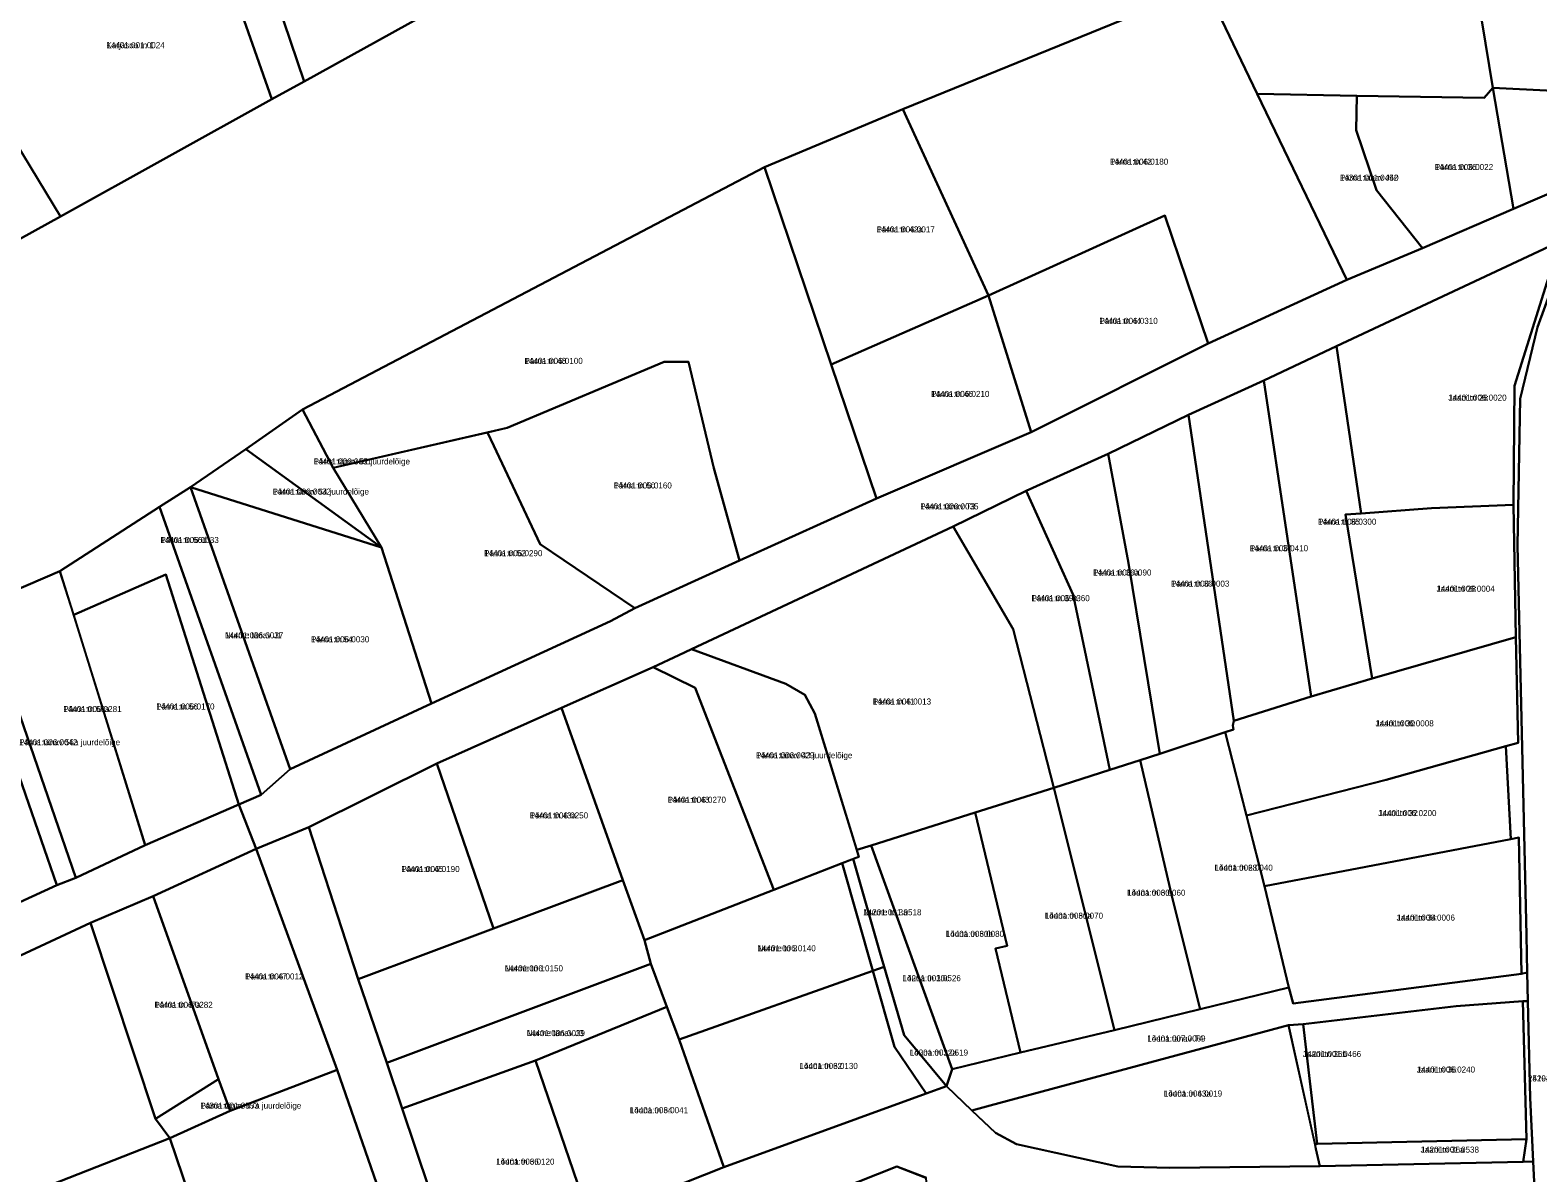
# Model space of a CAD drawing. Extents: x 640657 to 665127, y 6395726 to 6426831.
# Drawn here: x 649552.6 to 649927.6, y 6411820.4 to 6412104.6 of the extents above; entities that cross this region are included whole.
import ezdxf

# ---------------------------------------------------------------- set-up
doc = ezdxf.new("R2010")
doc.units = 0
for name, color, linetype in [('L_AADRESS', 7, 'Continuous'), ('PIIR', 7, 'Continuous'), ('TUNNUS', 7, 'Continuous')]:
    doc.layers.add(name, color=color, linetype=linetype)

msp = doc.modelspace()

# ---------------------------------------------------------------- linework, layer by layer
at = {"layer": 'PIIR'}
for points in [[(649378.03, 6411957.6), (649560.17, 6412058.25), (649612.7, 6412087.46), (649620.75, 6412091.85), (649650.44, 6412108.25), (649668.58, 6412116.67), (649691.67, 6412127.38), (649718.88, 6412138.69), (649748.94, 6412151.16), (649770.59, 6412160.14), (649810.5, 6412176.7), (649842.91, 6412190.15), (649874.08, 6412203.09), (649950.67, 6412234.89)], [(649966.63, 6412168.97), (649907.99, 6412141.34), (649844.88, 6412115.63), (649769.67, 6412084.97), (649735.24, 6412070.53), (649620.31, 6412010.25), (649606.21, 6412000.36), (649592.49, 6411990.94), (649584.81, 6411986.06), (649559.96, 6411970.08), (649540.51, 6411961.7)], [(649933.03, 6412052.06), (649877.52, 6412026), (649859.42, 6412017.5), (649840.64, 6412008.94), (649820.71, 6411999.22), (649800.34, 6411990), (649782.11, 6411981.17), (649717.09, 6411950.68), (649713.95, 6411949.19), (649707.53, 6411946.14), (649684.71, 6411936.04), (649653.72, 6411922.25), (649621.95, 6411906.37), (649608.8, 6411901), (649604.48, 6411912.01), (649610.06, 6411914.41), (649617.3, 6411920.82), (649652.39, 6411937.15), (649696.95, 6411957.65), (649703.01, 6411960.84), (649729.05, 6411972.66), (649763.1, 6411988.14), (649801.51, 6412004.58), (649845.57, 6412026.66), (649880.01, 6412042.47), (649898.84, 6412050.36), (649921.48, 6412060.15), (649934.02, 6412065.58)], [(649926.77, 6411814.86), (649926.38, 6411823.2), (649925.63, 6411839.07), (649925.1, 6411863.1), (649924.9, 6411870.2), (649924.73, 6411879.55), (649922.49, 6411976.44), (649923.17, 6412012.91), (649927.45, 6412030.71), (649935.7, 6412053.2)], [(649648.59, 6411789.41), (649628.94, 6411846.06), (649608.8, 6411901), (649621.95, 6411906.37), (649634.14, 6411868.56), (649641.33, 6411847.78), (649645.1, 6411836.4), (649658.55, 6411796.48)], [(649691.9, 6411808.65), (649725.14, 6411821.84), (649775.45, 6411840.16), (649780.5, 6411842), (649786.76, 6411835.93), (649792.65, 6411830.35), (649797.92, 6411827.51), (649823.13, 6411821.98), (649836.01, 6411821.63), (649873.34, 6411822.07), (649923.92, 6411823.15), (649926.38, 6411823.2), (649926.77, 6411814.86)], [(649775.5, 6411819.2), (649768.14, 6411821.97), (649730.09, 6411806.9)]]:
    msp.add_lwpolyline(points, dxfattribs=at)
for points in [[(649593.55, 6412141.97), (649586.4, 6412168.82), (649596.55, 6412170.1), (649613.03, 6412114.94), (649613.92, 6412111.92), (649620.75, 6412091.85), (649612.7, 6412087.46)], [(649907.99, 6412141.34), (649966.63, 6412168.97), (649944.74, 6412088.85), (649916.39, 6412090.28)], [(649524.06, 6412120.99), (649593.55, 6412141.97), (649612.7, 6412087.46), (649560.17, 6412058.25), (649535.55, 6412098.81)], [(649844.88, 6412115.63), (649907.99, 6412141.34), (649916.39, 6412090.28), (649914.19, 6412087.74), (649882.56, 6412088.24), (649857.79, 6412088.79)], [(649650.44, 6412108.25), (649620.75, 6412091.85), (649613.92, 6412111.92), (649618.8, 6412113.87), (649644.9, 6412124.06)], [(649769.67, 6412084.97), (649844.88, 6412115.63), (649857.79, 6412088.79), (649880.01, 6412042.47), (649845.57, 6412026.66), (649834.75, 6412058.52), (649790.94, 6412038.61)], [(649378.03, 6411957.6), (649387.65, 6412060.41), (649477.25, 6412088.89), (649479.92, 6412080.49), (649486.11, 6412082.25), (649535.55, 6412098.81), (649560.17, 6412058.25)], [(649857.79, 6412088.79), (649882.56, 6412088.24), (649882.38, 6412079.69), (649887.45, 6412064.8), (649898.84, 6412050.36), (649880.01, 6412042.47)], [(649882.56, 6412088.24), (649914.19, 6412087.74), (649916.39, 6412090.28), (649921.48, 6412060.15), (649898.84, 6412050.36), (649887.45, 6412064.8), (649882.38, 6412079.69)], [(649921.48, 6412060.15), (649916.39, 6412090.28), (649944.74, 6412088.85), (649939.25, 6412068.88), (649934.02, 6412065.58)], [(649735.24, 6412070.53), (649769.67, 6412084.97), (649790.94, 6412038.61), (649751.82, 6412021.41)], [(649620.31, 6412010.25), (649735.24, 6412070.53), (649751.82, 6412021.41), (649763.1, 6411988.14), (649729.05, 6411972.66), (649722.61, 6411995.65), (649716.35, 6412022.12), (649710.24, 6412022.07), (649671.22, 6412005.67), (649628, 6411995.77)], [(649790.94, 6412038.61), (649834.75, 6412058.52), (649845.57, 6412026.66), (649801.51, 6412004.58)], [(649883.62, 6411984.4), (649877.52, 6412026), (649933.03, 6412052.06), (649921.73, 6412016.17), (649921.49, 6411986.55), (649901.11, 6411985.71)], [(649935.7, 6412053.2), (649927.45, 6412030.71), (649923.17, 6412012.91), (649922.49, 6411976.44), (649924.73, 6411879.55), (649924.9, 6411870.2), (649923.51, 6411869.9), (649922.81, 6411903.79), (649920.86, 6411903.43), (649919.62, 6411926.52), (649922.7, 6411927.31), (649922.04, 6411953.62), (649921.49, 6411986.55), (649921.73, 6412016.17), (649933.03, 6412052.06)], [(649751.82, 6412021.41), (649790.94, 6412038.61), (649801.51, 6412004.58), (649763.1, 6411988.15)], [(649859.42, 6412017.5), (649877.52, 6412026), (649883.62, 6411984.4), (649879.68, 6411984.1), (649886.37, 6411943.31), (649871.2, 6411938.88)], [(649667.89, 6412001.23), (649666.33, 6412004.54), (649671.22, 6412005.67), (649710.24, 6412022.07), (649716.35, 6412022.12), (649722.61, 6411995.65), (649729.05, 6411972.66), (649703.01, 6411960.84), (649679.45, 6411976.75)], [(649851.97, 6411932.85), (649840.64, 6412008.94), (649859.42, 6412017.5), (649871.2, 6411938.88)], [(649606.21, 6412000.36), (649620.31, 6412010.25), (649628, 6411995.77), (649639.96, 6411975.96)], [(649840.64, 6412008.94), (649851.97, 6411932.85), (649851.71, 6411931.63), (649851.83, 6411930.66), (649849.82, 6411929.99), (649833.57, 6411924.64), (649825.73, 6411972.01), (649820.71, 6411999.22)], [(649639.96, 6411975.96), (649628, 6411995.77), (649666.33, 6412004.54), (649667.89, 6412001.23), (649679.45, 6411976.75), (649703.01, 6411960.84), (649696.95, 6411957.65), (649652.39, 6411937.15)], [(649592.49, 6411990.94), (649606.21, 6412000.36), (649639.96, 6411975.96)], [(649800.34, 6411990), (649820.71, 6411999.22), (649825.73, 6411972.01), (649833.57, 6411924.64), (649828.65, 6411923.03), (649821.1, 6411920.61), (649811.98, 6411964.14)], [(649584.81, 6411986.06), (649592.49, 6411990.94), (649617.3, 6411920.82), (649610.06, 6411914.41)], [(649592.49, 6411990.94), (649639.96, 6411975.96), (649652.39, 6411937.15), (649617.3, 6411920.82)], [(649782.11, 6411981.17), (649800.34, 6411990), (649811.98, 6411964.14), (649821.1, 6411920.61), (649807.22, 6411916.19), (649797.04, 6411955.66)], [(649559.96, 6411970.08), (649584.81, 6411986.06), (649610.06, 6411914.41), (649604.48, 6411912.01), (649586.36, 6411969.22), (649563.44, 6411959.16)], [(649921.49, 6411986.55), (649922.04, 6411953.62), (649886.37, 6411943.31), (649879.68, 6411984.1), (649883.62, 6411984.4), (649901.11, 6411985.71)], [(649782.11, 6411981.17), (649797.04, 6411955.66), (649807.22, 6411916.19), (649787.64, 6411910.04), (649761.73, 6411901.81), (649758.2, 6411900.7), (649747.73, 6411934.68), (649745.27, 6411939.26), (649740.53, 6411941.99), (649717.09, 6411950.68)], [(649559.96, 6411970.08), (649581.19, 6411901.91), (649563.96, 6411893.77), (649540.51, 6411961.7)], [(649563.44, 6411959.16), (649586.36, 6411969.22), (649604.48, 6411912.01), (649581.19, 6411901.91)], [(649535.8, 6411959.57), (649540.51, 6411961.7), (649563.96, 6411893.77), (649559.24, 6411891.92)], [(649515.01, 6411950.07), (649535.8, 6411959.57), (649559.24, 6411891.92), (649537.7, 6411882.08), (649535.3, 6411888.7), (649518.3, 6411941)], [(649707.53, 6411946.14), (649713.95, 6411949.19), (649717.09, 6411950.68), (649740.53, 6411941.99), (649745.27, 6411939.26), (649747.73, 6411934.68), (649758.68, 6411899.03), (649754.57, 6411897.43), (649737.58, 6411890.77), (649718, 6411941.02)], [(649922.04, 6411953.62), (649922.7, 6411927.31), (649919.62, 6411926.52), (649889.84, 6411918.12), (649855.11, 6411909.28), (649849.82, 6411929.99), (649851.83, 6411930.66), (649851.71, 6411931.63), (649851.97, 6411932.85), (649871.2, 6411938.88), (649886.37, 6411943.31)], [(649718, 6411941.02), (649737.58, 6411890.77), (649705.37, 6411878.3), (649700.02, 6411893.23), (649684.71, 6411936.04), (649707.53, 6411946.14)], [(649653.72, 6411922.25), (649684.71, 6411936.04), (649700.02, 6411893.23), (649667.86, 6411881.18)], [(649859.59, 6411891.74), (649865.64, 6411866.46), (649843.6, 6411861.14), (649836.67, 6411888.54), (649828.65, 6411923.03), (649833.57, 6411924.64), (649849.82, 6411929.99)], [(649855.11, 6411909.28), (649889.84, 6411918.12), (649919.62, 6411926.52), (649920.86, 6411903.43), (649859.59, 6411891.74)], [(649621.95, 6411906.37), (649653.72, 6411922.25), (649667.86, 6411881.18), (649634.14, 6411868.56)], [(649836.67, 6411888.54), (649843.6, 6411861.14), (649822.23, 6411855.89), (649807.22, 6411916.19), (649821.1, 6411920.61), (649828.65, 6411923.03)], [(649792.65, 6411876.17), (649795.61, 6411876.89), (649787.64, 6411910.04), (649807.22, 6411916.19), (649822.23, 6411855.89), (649798.89, 6411850.3)], [(649359.6, 6411800), (649461.18, 6411845.56), (649461.5, 6411845.7), (649492.04, 6411860.8), (649511.66, 6411869.3), (649537.7, 6411882.08), (649559.24, 6411891.92), (649563.96, 6411893.77), (649581.19, 6411901.91), (649604.48, 6411912.01), (649608.8, 6411901), (649583.2, 6411889.18), (649567.57, 6411882.62), (649537.67, 6411868.66), (649501.41, 6411851.98), (649491.81, 6411847.78), (649460.08, 6411833.74), (649365.41, 6411791.58), (649361.7, 6411789.91)], [(649787.64, 6411910.04), (649795.61, 6411876.89), (649792.65, 6411876.17), (649798.89, 6411850.3), (649781.86, 6411846.2), (649761.73, 6411901.81)], [(649758.68, 6411899.03), (649758.2, 6411900.7), (649761.73, 6411901.81), (649781.86, 6411846.2), (649780.5, 6411842), (649769.94, 6411854.67), (649764.96, 6411871.63), (649763.9, 6411875.25), (649757.26, 6411898.48)], [(649922.81, 6411903.79), (649923.51, 6411869.9), (649866.67, 6411862.49), (649865.64, 6411866.46), (649859.59, 6411891.74), (649920.86, 6411903.43)], [(649608.8, 6411901), (649628.94, 6411846.06), (649602.34, 6411835.82), (649599.45, 6411843.73), (649583.2, 6411889.18)], [(649757.26, 6411898.48), (649763.9, 6411875.25), (649764.96, 6411871.63), (649762.2, 6411870.66), (649754.57, 6411897.43)], [(649706.98, 6411872.42), (649705.37, 6411878.3), (649737.58, 6411890.77), (649754.57, 6411897.43), (649762.2, 6411870.66), (649714.03, 6411853.59), (649710.9, 6411861.7)], [(649634.14, 6411868.56), (649667.86, 6411881.18), (649700.02, 6411893.23), (649705.37, 6411878.3), (649706.98, 6411872.42), (649641.33, 6411847.78)], [(649567.57, 6411882.62), (649583.2, 6411889.18), (649599.45, 6411843.73), (649583.75, 6411833.86)], [(649492.1, 6411846.32), (649491.81, 6411847.78), (649501.41, 6411851.98), (649537.67, 6411868.66), (649567.57, 6411882.62), (649583.75, 6411833.86), (649587.32, 6411829.02), (649552.9, 6411815.48), (649514.43, 6411799.9), (649504.11, 6411795.75), (649503.76, 6411797.21), (649502.88, 6411801.17)], [(649641.33, 6411847.78), (649706.98, 6411872.42), (649710.9, 6411861.7), (649678.32, 6411848.32), (649645.1, 6411836.4)], [(649762.2, 6411870.66), (649764.96, 6411871.63), (649769.94, 6411854.67), (649780.5, 6411842), (649775.45, 6411840.16), (649767.53, 6411851.74)], [(649767.53, 6411851.74), (649775.45, 6411840.16), (649725.14, 6411821.84), (649714.03, 6411853.59), (649762.2, 6411870.66)], [(649781.86, 6411846.2), (649798.89, 6411850.3), (649822.23, 6411855.89), (649843.6, 6411861.14), (649865.64, 6411866.46), (649866.67, 6411862.49), (649923.51, 6411869.9), (649924.9, 6411870.2), (649925.1, 6411863.1), (649923.8, 6411863.1), (649907.2, 6411861.9), (649869.22, 6411857.39), (649865.54, 6411857.14), (649791.37, 6411837.17), (649786.76, 6411835.93), (649780.5, 6411842)], [(649678.32, 6411848.32), (649710.9, 6411861.7), (649714.03, 6411853.59), (649725.14, 6411821.84), (649691.9, 6411808.65)], [(649924.69, 6411828.8), (649872.69, 6411827.59), (649869.22, 6411857.39), (649907.2, 6411861.9), (649923.8, 6411863.1)], [(649925.1, 6411863.1), (649925.63, 6411839.07), (649926.38, 6411823.2), (649923.92, 6411823.15), (649924.69, 6411828.8), (649923.8, 6411863.1)], [(649786.76, 6411835.93), (649791.37, 6411837.17), (649865.54, 6411857.14), (649872.38, 6411826.38), (649873.34, 6411822.07), (649836.01, 6411821.63), (649823.13, 6411821.98), (649797.92, 6411827.51), (649792.65, 6411830.35)], [(649872.14, 6411827.47), (649865.54, 6411857.14), (649869.22, 6411857.39), (649872.69, 6411827.59)], [(649587.32, 6411829.02), (649602.34, 6411835.82), (649628.94, 6411846.06), (649648.59, 6411789.41), (649606.41, 6411772.84)], [(649658.55, 6411796.48), (649645.1, 6411836.4), (649678.32, 6411848.32), (649691.9, 6411808.65)], [(649602.34, 6411835.82), (649587.32, 6411829.02), (649583.75, 6411833.86), (649599.45, 6411843.73)], [(649552.9, 6411815.48), (649587.32, 6411829.02), (649606.41, 6411772.84), (649568.62, 6411758.44)], [(649872.14, 6411827.47), (649872.69, 6411827.59), (649924.69, 6411828.8), (649923.92, 6411823.15), (649873.34, 6411822.07), (649872.38, 6411826.38)], [(649730.09, 6411806.9), (649768.14, 6411821.97), (649775.35, 6411819.18), (649780.47, 6411751.28), (649746.12, 6411740.15), (649738.04, 6411783.15)]]:
    msp.add_lwpolyline(points, close=True, dxfattribs=at)

# ---------------------------------------------------------------- texts
at = {"layer": 'L_AADRESS'}
for s, p in [('Karjasoo tn 1', (649571.57, 6412100.11)), ('Pärna tn 42', (649821.13, 6412071.15)), ('Pärna tn 36', (649901.93, 6412069.81)), ('Pärna tänav J40', (649878.32, 6412067.17)), ('Pärna tn 42a', (649763.09, 6412054.29)), ('Pärna tn 44', (649818.52, 6412031.55)), ('Pärna tn 48', (649675.53, 6412021.6)), ('Pärna tn 46', (649776.66, 6412013.38)), ('Jaani tn 26', (649905.28, 6412012.46)), ('Pärna tänav 52 juurdelõige', (649623.09, 6411996.59)), ('Pärna tn 50', (649697.69, 6411990.61)), ('Pärna tänav 54 juurdelõige', (649612.89, 6411989.09)), ('Pärna tänav T3', (649773.96, 6411985.4)), ('Pärna tn 35', (649872.89, 6411981.6)), ('Pärna tn 56d', (649585.01, 6411977.06)), ('Pärna tn 37', (649855.92, 6411975)), ('Pärna tn 52', (649665.5, 6411973.77)), ('Pärna tn 39a', (649816.96, 6411968.96)), ('Pärna tn 39', (649836.34, 6411966.2)), ('Jaani tn 28', (649902.34, 6411964.93)), ('Pärna tn 39b', (649801.61, 6411962.58)), ('Nurme tänav J1', (649601.05, 6411953.35)), ('Pärna tn 54', (649622.44, 6411952.35)), ('Pärna tn 56a', (649560.85, 6411935)), ('Pärna tn 56', (649583.96, 6411935.64)), ('Pärna tn 41', (649762.16, 6411936.88)), ('Jaani tn 30', (649887.16, 6411931.45)), ('Pärna tänav 56a juurdelõige', (649549.88, 6411926.75)), ('Pärna tänav 43 juurdelõige', (649733.11, 6411923.5)), ('Pärna tn 43', (649711.14, 6411912.45)), ('Pärna tn 43a', (649676.87, 6411908.55)), ('Jaani tn 32', (649887.85, 6411909.13)), ('Pärna tn 45', (649644.91, 6411895.22)), ('Lõuna tn 28', (649847.14, 6411895.55)), ('Lõuna tn 30', (649825.41, 6411889.33)), ('Nurme tn 3a', (649759.77, 6411884.46)), ('Lõuna tn 30a', (649804.93, 6411883.61)), ('Jaani tn 34', (649892.44, 6411883.14)), ('Lõuna tn 30b', (649780.31, 6411879.1)), ('Nurme tn 3', (649733.48, 6411875.51)), ('Nurme tn 1', (649670.61, 6411870.51)), ('Pärna tn 47', (649606.07, 6411868.5)), ('Lõuna tn 30c', (649769.56, 6411868.07)), ('Pärna tn 47a', (649583.51, 6411861.45)), ('Nurme tänav J3', (649676.07, 6411854.41)), ('Lõuna tänav T4', (649830.42, 6411853.07)), ('Lõuna tn 32a', (649771.35, 6411849.57)), ('Jaani tn 36b', (649869.11, 6411849.23)), ('Lõuna tn 32', (649743.94, 6411846.25)), ('Jaani tn 36', (649897.44, 6411845.35)), ('25194 Antsla-Haabsaare tee L10', (649925.09, 6411843.14)), ('Pärna tänav 47a juurdelõige', (649594.94, 6411836.38)), ('Lõuna tn 43a', (649834.54, 6411839.38)), ('Lõuna tn 34', (649701.73, 6411835.24)), ('Jaani tn 36a', (649898.41, 6411825.44)), ('Lõuna tn 36', (649668.5, 6411822.45))]:
    msp.add_text(s, height=1.5, dxfattribs=at).set_placement(p)
at = {"layer": 'TUNNUS'}
for s, p in [('14401:001:0024', (649571.57, 6412100.11)), ('14401:006:0180', (649821.13, 6412071.15)), ('14401:006:0022', (649901.93, 6412069.81)), ('14301:001:0452', (649878.32, 6412067.17)), ('14401:006:0017', (649763.09, 6412054.29)), ('14401:006:0310', (649818.52, 6412031.55)), ('14401:006:0100', (649675.53, 6412021.6)), ('14401:006:0210', (649776.66, 6412013.38)), ('14401:006:0020', (649905.28, 6412012.46)), ('14401:006:0031', (649623.09, 6411996.59)), ('14401:006:0160', (649697.69, 6411990.61)), ('14401:006:0032', (649612.89, 6411989.09)), ('14401:006:0035', (649773.96, 6411985.4)), ('14401:006:0300', (649872.89, 6411981.6)), ('14401:006:0033', (649585.01, 6411977.06)), ('14401:006:0410', (649855.92, 6411975)), ('14401:006:0290', (649665.5, 6411973.77)), ('14401:006:0090', (649816.96, 6411968.96)), ('14401:006:0003', (649836.34, 6411966.2)), ('14401:006:0004', (649902.34, 6411964.93)), ('14401:006:0360', (649801.61, 6411962.58)), ('14401:006:0037', (649601.05, 6411953.35)), ('14401:006:0030', (649622.44, 6411952.35)), ('14401:006:0281', (649560.85, 6411935)), ('14401:006:0170', (649583.96, 6411935.64)), ('14401:006:0013', (649762.16, 6411936.88)), ('14401:006:0008', (649887.16, 6411931.45)), ('14401:006:0042', (649549.88, 6411926.75)), ('14401:006:0029', (649733.11, 6411923.5)), ('14401:006:0270', (649711.14, 6411912.45)), ('14401:006:0250', (649676.87, 6411908.55)), ('14401:006:0200', (649887.85, 6411909.13)), ('14401:006:0190', (649644.91, 6411895.22)), ('14401:006:0040', (649847.14, 6411895.55)), ('14401:006:0060', (649825.41, 6411889.33)), ('14201:001:0518', (649759.77, 6411884.46)), ('14401:006:0070', (649804.93, 6411883.61)), ('14401:006:0006', (649892.44, 6411883.14)), ('14401:006:0080', (649780.31, 6411879.1)), ('14401:006:0140', (649733.48, 6411875.51)), ('14401:006:0150', (649670.61, 6411870.51)), ('14401:006:0012', (649606.07, 6411868.5)), ('14201:001:0526', (649769.56, 6411868.07)), ('14401:006:0282', (649583.51, 6411861.45)), ('14401:006:0039', (649676.07, 6411854.41)), ('14401:007:0069', (649830.42, 6411853.07)), ('14201:001:0519', (649771.35, 6411849.57)), ('14201:001:0466', (649869.11, 6411849.23)), ('14401:006:0130', (649743.94, 6411846.25)), ('14401:006:0240', (649897.44, 6411845.35)), ('14201:001:0252', (649925.09, 6411843.14)), ('14301:001:0553', (649594.94, 6411836.38)), ('14401:006:0019', (649834.54, 6411839.38)), ('14401:006:0041', (649701.73, 6411835.24)), ('14201:001:0538', (649898.41, 6411825.44)), ('14401:006:0120', (649668.5, 6411822.45))]:
    msp.add_text(s, height=1.5, dxfattribs=at).set_placement(p)

doc.saveas('drawing.dxf')
